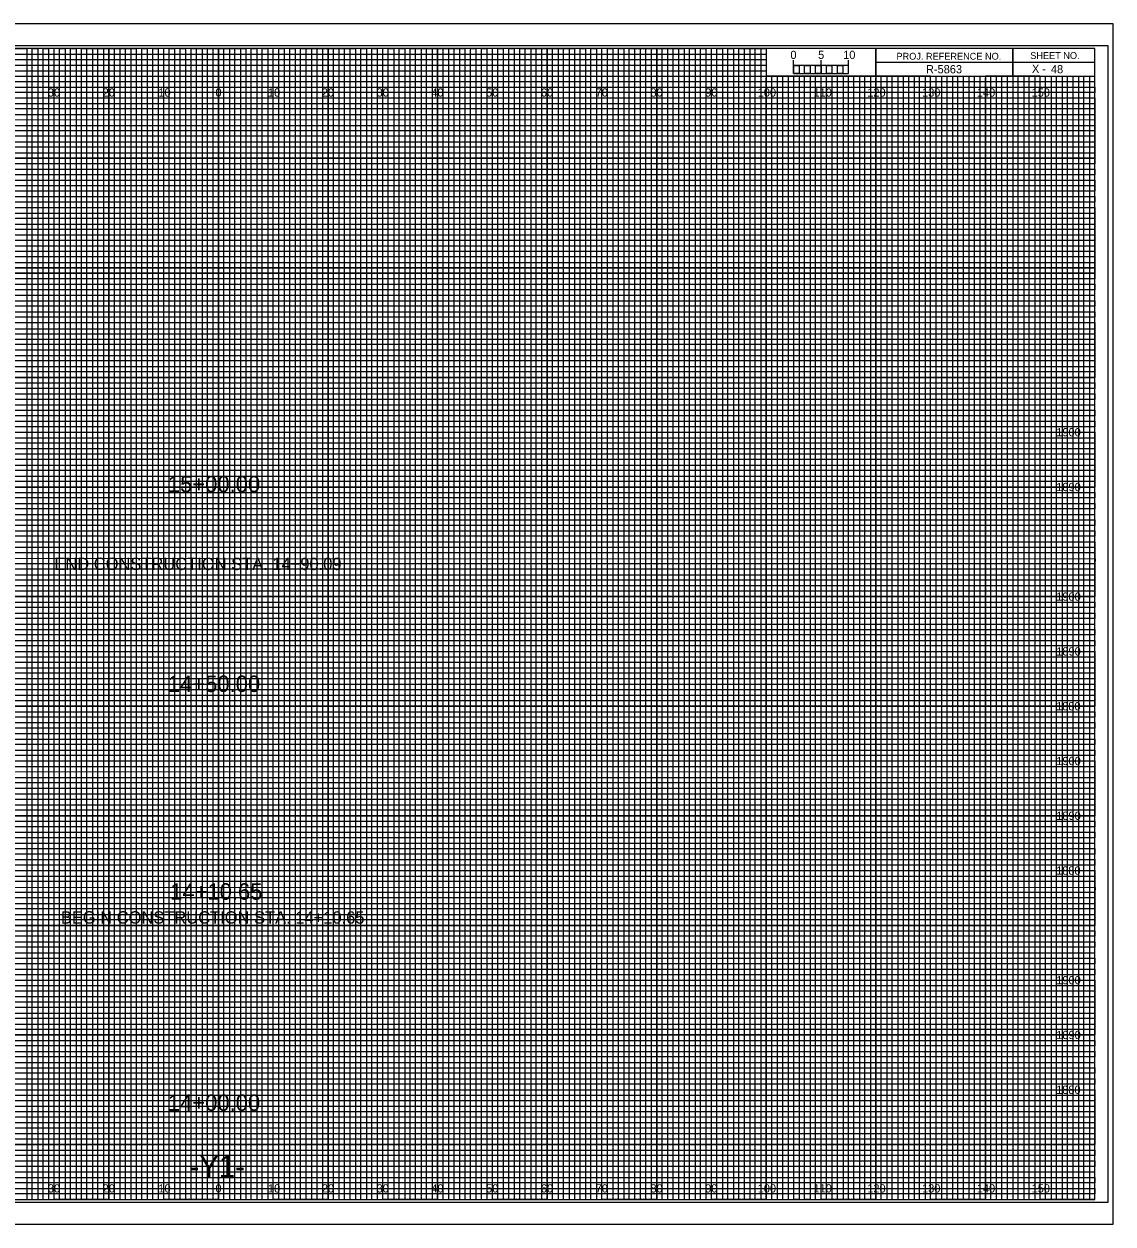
# Model space of a CAD drawing. Extents: x -13 to 323, y -4 to 214.
# Drawn here: x 124.5 to 323.3, y -4.5 to 214.5 of the extents above; entities that cross this region are included whole.
import ezdxf

# ---------------------------------------------------------------- set-up
doc = ezdxf.new("R2010")
doc.units = 0
for name, color, linetype in [('Prop XS Alignment Label', 7, 'Continuous'), ('Prop XS Bar Scale Labels', 7, 'Continuous'), ('Prop XS Elevation Labels', 7, 'Continuous'), ('Prop XS Offset Labels', 7, 'Continuous'), ('Prop XS Project Number', 7, 'Continuous'), ('Prop XS SE Text', 7, 'Continuous'), ('Prop XS Sheet Number', 7, 'Continuous'), ('Prop XS Station Labels', 7, 'Continuous'), ('Sheet Cross Section CELL', 7, 'Continuous'), ('Sheet Cross Section Grid Major CELL', 7, 'Continuous'), ('Sheet Cross Section Grid Middle CELL', 7, 'Continuous'), ('Sheet Cross Section Grid Minor 1 CELL', 7, 'Continuous'), ('Sheet Cross Section Grid Minor 2 CELL', 7, 'Continuous'), ('Sheet Cross Section Scale CELL', 7, 'Continuous'), ('Sheet Cutting Line CELL', 7, 'Continuous'), ('Sheet DOT Grid CELL', 7, 'Continuous'), ('Sheet Plot Border Inside CELL', 7, 'Continuous'), ('Sheet Plot Border Outside CELL', 7, 'Continuous')]:
    doc.layers.add(name, color=color, linetype=linetype)

msp = doc.modelspace()

# ---------------------------------------------------------------- linework, layer by layer
at = {"layer": 'Sheet Cross Section CELL'}
for p, q in [((305, 210), (305, 205)), ((305, 205), (305, 210)), ((280, 207.5), (280, 205)), ((320, 207.49), (280, 207.49)), ((280, 205), (320, 205))]:
    msp.add_line(p, q, dxfattribs=at)
for points in [[(320, 210), (0, 210), (0, 0), (320, 0)], [(280, 210), (260, 210), (260, 205.03), (280, 205.03)], [(320, 210), (280, 210), (280, 205), (320, 205)]]:
    msp.add_lwpolyline(points, close=True, dxfattribs=at)
at = {"layer": 'Sheet Cross Section Grid Major CELL'}
for p, q in [((130, 210), (120, 210)), ((130, 0), (130, 210)), ((150, 210), (140, 210)), ((140, 210), (140, 0)), ((150, 0), (150, 210)), ((170, 210), (160, 210)), ((160, 210), (160, 0)), ((170, 0), (170, 210)), ((190, 210), (180, 210)), ((180, 210), (180, 0)), ((190, 0), (190, 210)), ((210, 210), (200, 210)), ((200, 210), (200, 0)), ((210, 0), (210, 210)), ((230, 210), (220, 210)), ((220, 210), (220, 0)), ((230, 0), (230, 210)), ((250, 210), (240, 210)), ((240, 210), (240, 0)), ((250, 0), (250, 210)), ((260, 210), (260, 0)), ((270, 0), (270, 205)), ((290, 205), (280, 205)), ((280, 205), (280, 0)), ((290, 0), (290, 205)), ((310, 205), (300, 205)), ((300, 205), (300, 0)), ((310, 0), (310, 205)), ((140, 0), (130, 0)), ((160, 0), (150, 0)), ((180, 0), (170, 0)), ((200, 0), (190, 0)), ((220, 0), (210, 0)), ((240, 0), (230, 0)), ((260, 0), (250, 0)), ((280, 0), (270, 0)), ((300, 0), (290, 0)), ((320, 0), (310, 0)), ((320, 0), (320, 0))]:
    msp.add_line(p, q, dxfattribs=at)
for points in [[(0, 200), (320, 200), (320, 190), (0, 190)], [(0, 180), (320, 180), (320, 170), (0, 170)], [(0, 160), (320, 160), (320, 150), (0, 150)], [(0, 140), (320, 140), (320, 130), (0, 130)], [(0, 120), (320, 120), (320, 110), (0, 110)], [(0, 100), (320, 100), (320, 90), (0, 90)], [(0, 80), (320, 80), (320, 70), (0, 70)], [(0, 60), (320, 60), (320, 50), (0, 50)], [(0, 40), (320, 40), (320, 30), (0, 30)], [(0, 20), (320, 20), (320, 10), (0, 10)]]:
    msp.add_lwpolyline(points, dxfattribs=at)
at = {"layer": 'Sheet Cross Section Grid Middle CELL'}
for points in [[(115, 210), (125, 210), (125, 0), (135, 0), (135, 210), (145, 210), (145, 0), (155, 0), (155, 210), (165, 210), (165, 0), (175, 0), (175, 210), (185, 210), (185, 0), (195, 0), (195, 210), (205, 210), (205, 0), (215, 0), (215, 210), (225, 210), (225, 0), (235, 0), (235, 210), (245, 210), (245, 0), (255, 0), (255, 210), (259.93, 210), (260, 210), (260, 205), (264.99, 205), (264.99, 0), (275, 0), (275, 205), (285, 205), (285, 0), (295, 0), (295, 205), (305, 205), (305, 0), (315, 0), (315, 205)], [(0, 205), (275, 205)], [(0, 185), (320, 185), (320, 195), (0, 195)], [(0, 165), (320, 165), (320, 175), (0, 175)], [(0, 145), (320, 145), (320, 155), (0, 155)], [(0, 125), (320, 125), (320, 135), (0, 135)], [(0, 105), (320, 105), (320, 115), (0, 115)], [(0, 85), (320, 85), (320, 95), (0, 95)], [(0, 65), (320, 65), (320, 75), (0, 75)], [(0, 45), (320, 45), (320, 55), (0, 55)], [(0, 25), (320, 25), (320, 35), (0, 35)], [(0, 5), (320, 5), (320, 15), (0, 15)]]:
    msp.add_lwpolyline(points, dxfattribs=at)
at = {"layer": 'Sheet Cross Section Grid Minor 1 CELL'}
for p, q in [((0, 209), (260, 209)), ((260, 209), (260, 207.98)), ((260, 207.98), (0, 207.98)), ((0, 207), (260, 207)), ((260, 205.89), (0, 205.89)), ((260, 207), (260, 205.89)), ((0, 204), (320, 204))]:
    msp.add_line(p, q, dxfattribs=at)
for points in [[(0, 203), (270, 203), (320, 203), (320, 202), (0, 202)], [(0, 201), (320, 201), (320, 199), (0, 199)], [(0, 198), (320, 198), (320, 197), (0, 196.98)], [(0, 196), (320, 196), (320, 194), (0, 194)], [(0, 193), (320, 193), (320, 192), (0, 192)], [(0, 191), (320, 191), (320, 189), (0, 189)], [(0, 188), (320, 188), (320, 187), (0, 187)], [(0, 186), (320, 186), (320, 184), (0, 184)], [(0, 183), (320, 183), (320, 182), (0, 182)], [(0, 181), (320, 181), (320, 179), (0, 179)], [(0, 178), (320, 178), (320, 177), (0, 177)], [(0, 176), (320, 176), (320, 173.95), (320, 173), (320, 172), (0, 172)], [(0, 174), (320, 174), (320, 173), (0, 173)], [(0, 171), (320, 171), (320, 169), (0, 169.03)], [(0, 169.03), (320, 169), (320, 168), (0, 168)], [(0, 167), (320, 167), (320, 166), (0, 166)], [(0, 164), (320, 164), (320, 163), (0, 163)], [(0, 162), (320, 162), (320, 161), (0, 161)], [(-0.07, 158.89), (320, 158.89), (320, 157.88), (-0.07, 157.88)], [(0, 157), (320, 157), (320, 156), (0, 156)], [(0, 154), (320, 154), (320, 153), (0, 153)], [(0, 152), (320, 152), (320, 151), (0, 151)], [(0, 149), (320, 149), (320, 148), (0, 148)], [(0, 147), (320, 147), (320, 146), (0, 146)], [(0, 144), (320, 144), (320, 143), (0, 143)], [(0, 142), (320, 142), (320, 141), (0, 141)], [(0, 139), (320, 139), (319.99, 137.98), (0, 138)], [(0, 137), (320, 137), (320, 136), (0, 136)], [(0, 134), (320, 134), (320, 133), (0, 133)], [(0, 132), (320, 132), (320, 131), (0, 131)], [(0, 129), (320, 129), (320, 128), (0, 128)], [(0, 127), (320, 127), (320, 126), (0, 126)], [(0, 124), (320, 124), (320, 123), (0, 123)], [(0, 122), (320, 122), (320, 121), (0, 121)], [(0, 119), (320, 119), (320, 118), (0, 118)], [(0, 116.99), (320.07, 116.91), (320, 116), (0, 116)], [(0, 114), (320, 114), (320, 113), (0, 113)], [(0, 112), (320, 112), (320, 111), (0, 111)], [(0, 109), (320, 109), (320, 108), (0, 108)], [(0, 107), (320, 107), (320, 106), (0, 106)], [(0, 104), (320, 104), (320, 103), (0, 103)], [(0, 102), (320, 102), (320, 101), (0, 101)], [(0, 99), (320, 99), (320, 98), (0, 98)], [(0, 97), (320, 97), (320, 96), (0, 96)], [(0, 94), (320, 94), (320, 93), (0, 93)], [(0, 92), (320, 92), (320, 91), (0, 91)], [(0, 89), (320, 89), (320, 88), (0, 88)], [(0, 87), (320, 87), (320, 86), (0, 86)], [(0, 84), (320, 84), (320, 83), (0, 83)], [(0, 82), (320, 82), (320, 81), (0, 81)], [(0, 79), (320, 79), (319.99, 77.98), (0, 78)], [(0, 77), (320, 77), (320, 76), (0, 76)], [(0, 74), (320, 74), (320, 73), (0, 73)], [(0, 72), (320, 72), (320, 71), (0, 71)], [(0, 69), (320, 69), (320, 68), (0, 68)], [(0, 67), (320, 67), (320, 66), (0, 66)], [(0, 64), (320, 64), (320, 63), (0, 63)], [(0, 62), (320, 62), (320, 61), (0, 61)], [(0, 59), (320, 59), (320, 58), (0, 58)], [(0, 56.99), (320.07, 56.91), (320, 56), (0, 56)], [(0, 54), (320, 54), (320, 53), (0, 53)], [(0, 52), (320, 52), (320, 51), (0, 51)], [(0, 49), (320, 49), (320, 48), (0, 48)], [(0, 47), (320, 47), (320, 46), (0, 46)], [(0, 44), (320, 44), (320, 43), (0, 43)], [(0, 42), (320, 42), (320, 41), (0, 41)], [(0, 39), (320, 39), (320, 38), (0, 38)], [(0, 37), (320, 37), (320, 36), (0, 36)], [(0, 34), (320, 34), (320, 33), (0, 33)], [(0, 32), (320, 32), (320, 31), (0, 31)], [(0, 29), (320, 29), (320, 28), (0, 28)], [(0, 27), (320, 27), (320, 26), (0, 26)], [(0, 24), (320, 24), (320, 23), (0, 23)], [(0, 22), (320, 22), (320, 21), (0, 21)], [(0, 19), (320, 19), (320, 18), (0, 18)], [(0, 17), (320, 17), (320, 16), (0, 16)], [(0, 14), (320, 14), (320, 13), (0, 13)], [(0, 12), (320, 12), (320, 11), (0, 11)], [(0, 9), (320, 9), (320, 8), (0, 8)], [(0, 7), (320, 7), (320, 6), (0, 6)], [(0, 4), (320, 4), (320, 3), (0, 3)], [(0, 2), (320, 2), (320, 1), (0, 1)]]:
    msp.add_lwpolyline(points, dxfattribs=at)
at = {"layer": 'Sheet Cross Section Grid Minor 2 CELL'}
for p, q in [((267, 205), (266.01, 205)), ((266.01, 205), (266.01, 0)), ((267, 0), (267, 205)), ((269, 205), (268, 205)), ((268, 205), (268, 0)), ((269, 0), (269, 205)), ((266.01, 0), (265, 0)), ((268, 0), (267, 0))]:
    msp.add_line(p, q, dxfattribs=at)
for points in [[(125, 0), (126, 0), (126, 210), (127, 210), (127, 0)], [(127, 0), (128, 0), (128, 210), (129, 210), (129, 0)], [(130, 0), (131, 0), (131, 210), (132, 210), (132, 0)], [(132, 0), (133, 0), (133, 210), (134, 210), (134, 0)], [(135, 0), (136, 0), (136, 210), (137, 210), (137, 0)], [(137, 0), (138, 0), (138, 210), (139, 210), (139, 0)], [(140, 0), (141, 0), (141, 210), (142, 210), (142, 0)], [(142, 0), (143, 0), (143, 210), (144, 210), (144, 0)], [(145, 0), (146, 0), (146, 210), (147, 210), (147, 0)], [(147, 0), (148, 0), (148, 210), (149, 210), (149, 0)], [(150, 0), (151, 0), (151, 210), (152, 210), (152, 0)], [(152, 0), (153, 0), (153, 210), (154, 210), (154, 0)], [(155, 0), (156, 0), (156, 210), (157, 210), (157, 0)], [(157, 0), (158, 0), (158, 210), (159, 210), (159, 0)], [(160, 0), (161, 0), (161, 210), (162, 210), (162, 0)], [(162, 0), (163, 0), (163, 210), (164, 210), (164, 0)], [(165, 0), (166, 0), (166, 210), (167, 210), (167, 0)], [(167, 0), (168, 0), (168, 210), (169, 210), (169, 0)], [(170, 0), (171, 0), (171, 210), (172, 210), (172, 0)], [(172, 0), (173, 0), (173, 210), (174, 210), (174, 0)], [(175, 0), (176, 0), (176, 210), (177, 210), (177, 0)], [(177, 0), (178, 0), (178, 210), (179, 210), (179, 0)], [(180, 0), (181, 0), (181, 210), (182, 210), (182, 0)], [(182, 0), (183, 0), (183, 210), (184, 210), (184, 0)], [(185, 0), (186, 0), (186, 210), (187, 210), (187, 0)], [(187, 0), (188, 0), (188, 210), (189, 210), (189, 0)], [(190, 0), (191, 0), (191, 210), (192, 210), (192, 0)], [(192, 0), (193, 0), (193, 210), (194, 210), (194, 0)], [(195, 0), (196, 0), (196, 210), (197, 210), (197, 0)], [(197, 0), (198, 0), (198, 210), (199, 210), (199, 0)], [(200, 0), (201, 0), (201, 210), (202, 210), (202, 0)], [(202, 0), (203, 0), (203, 210), (204, 210), (204, 0)], [(205, 0), (206, 0), (206, 210), (207, 210), (207, 0)], [(207, 0), (208, 0), (208, 210), (209, 210), (209, 0)], [(210, 0), (211, 0), (211, 210), (212, 210), (212, 0)], [(212, 0), (213, 0), (213, 210), (214, 210), (214, 0)], [(215, 0), (216, 0), (216, 210), (217, 210), (217, 0)], [(217, 0), (218, 0), (218, 210), (219, 210), (219, 0)], [(220, 0), (221, 0), (221, 210), (222, 210), (222, 0)], [(222, 0), (223, 0), (223, 210), (224, 210), (224, 0)], [(225, 0), (226, 0), (226, 210), (227, 210), (227, 0)], [(227, 0), (228, 0), (228, 210), (229, 210), (229, 0)], [(230, 0), (231, 0), (231, 210), (232, 210), (232, 0)], [(232, 0), (233, 0), (233, 210), (234, 210), (234, 0)], [(235, 0), (236, 0), (236, 210), (237, 210), (237, 0)], [(237, 0), (238, 0), (238, 210), (239, 210), (239, 0)], [(240, 0), (241, 0), (241, 210), (242, 210), (242, 0)], [(242, 0), (243, 0), (243, 210), (244, 210), (244, 0)], [(245, 0), (246, 0), (246, 210), (247, 210), (247, 0)], [(247, 0), (248, 0), (248, 210), (249, 210), (249, 0)], [(250, 0), (251, 0), (251, 210), (252, 210), (252, 0)], [(252, 0), (253, 0), (253, 210), (254, 210), (254, 0)], [(255, 0), (256, 0), (256, 210), (257, 210), (257, 0)], [(257, 0), (258, 0), (258, 210), (259, 210), (259, 0)], [(260, 0), (261, 0), (261, 205), (262.02, 205), (262.02, 0)], [(262, 0), (263, 0), (263, 205), (263.99, 205), (263.99, 0)], [(270, 0), (270.98, 0), (270.98, 205), (272, 205), (272, 0)], [(272, 0), (273, 0), (273, 205), (274.05, 205), (274.05, 0)], [(275, 0), (276, 0), (276, 205), (277, 205), (277, 0)], [(277, 0), (278, 0), (278, 205), (279, 205), (279, 0)], [(280, 0), (281, 0), (281, 205), (282, 205), (282, 0)], [(282, 0), (283, 0), (283, 205), (284, 205), (284, 0)], [(285, 0), (286, 0), (286, 205), (287, 205), (287, 0)], [(287, 0), (288, 0), (288, 205), (289, 205), (289, 0)], [(290, 0), (291, 0), (291, 205), (292, 205), (292, 0)], [(292, 0), (293, 0), (293, 205), (294, 205), (294, 0)], [(295, 0), (296, 0), (296, 205), (297, 205), (297, 0)], [(297, 0), (298, 0), (298, 205), (299, 205), (299, 0)], [(300, 0), (301, 0), (301, 205), (302, 205), (302, 0)], [(302, 0), (303, 0), (303, 205), (304, 205), (304, 0)], [(305, 0), (306, 0), (306, 205), (307, 205), (307, 0)], [(307, 0), (308, 0), (308, 205), (309, 205), (309, 0)], [(310, 0), (311, 0), (311, 205), (312, 205), (312, 0)], [(312, 0), (313, 0), (313, 205), (314, 205), (314, 0)], [(315, 0), (316, 0), (316, 205), (317, 205), (317, 0)], [(317, 0), (318, 0), (318, 205), (319, 205), (319, 0)]]:
    msp.add_lwpolyline(points, dxfattribs=at)
at = {"layer": 'Sheet Cross Section Scale CELL'}
for p, q in [((265, 205.49), (265, 207.9)), ((265, 206.9), (265, 207.9)), ((270, 205.49), (270, 207.9)), ((275, 205.49), (275, 207.9)), ((275, 206.9), (275, 207.9))]:
    msp.add_line(p, q, dxfattribs=at)
for points in [[(275, 206.9), (265, 206.9), (265, 205.49), (275, 205.49)], [(265, 206.9), (266, 206.9), (266, 205.49), (265, 205.49)], [(267, 206.9), (268, 206.9), (268, 205.49), (267, 205.49)], [(269, 206.9), (270, 206.9), (270, 205.49), (269, 205.49)], [(271, 206.9), (272, 206.9), (272, 205.49), (271, 205.49)], [(273, 206.9), (274, 206.9), (274, 205.49), (273, 205.49)]]:
    msp.add_lwpolyline(points, close=True, dxfattribs=at)
at = {"layer": 'Sheet Cutting Line CELL'}
for p, q in [((323.3, 214.5), (-13.4, 214.5)), ((-13.4, -4.5), (323.3, -4.5))]:
    msp.add_line(p, q, dxfattribs=at)
at = {"layer": 'Sheet DOT Grid CELL'}
for p, q in [((130, 0), (130, 210)), ((140, 0), (140, 210)), ((150, 0), (150, 210)), ((160, 0), (160, 210)), ((170, 0), (170, 210)), ((180, 0), (180, 210)), ((190, 0), (190, 210)), ((200, 0), (200, 210)), ((210, 0), (210, 210)), ((220, 0), (220, 210)), ((230, 0), (230, 210)), ((240, 0), (240, 210)), ((250, 0), (250, 210)), ((260, 0), (260, 204.69)), ((270, 0), (270, 204.69)), ((280, 0), (280, 204.69)), ((290, 0), (290, 204.69)), ((300, 0), (300, 204.69)), ((310, 0), (310, 204.69)), ((0, 200), (320, 200)), ((0, 190), (320, 190)), ((0, 180), (320, 180)), ((0, 170), (320, 170)), ((0, 160), (320, 160)), ((0, 150), (320, 150)), ((0, 140), (320, 140)), ((0, 130), (320, 130)), ((0, 120), (320, 120)), ((0, 110), (320, 110)), ((0, 100), (320, 100)), ((0, 90), (320, 90)), ((0, 80), (320, 80)), ((0, 70), (320, 70)), ((0, 60), (320, 60)), ((0, 50), (320, 50)), ((0, 40), (320, 40)), ((0, 30), (320, 30)), ((0, 20), (320, 20)), ((0, 10), (320, 10))]:
    msp.add_line(p, q, dxfattribs=at)
at = {"layer": 'Sheet Plot Border Inside CELL'}
msp.add_lwpolyline([(-10.8, -0.5), (322.4, -0.5), (322.4, 210.5), (-10.8, 210.5)], close=True, dxfattribs=at)
at = {"layer": 'Sheet Plot Border Outside CELL'}
msp.add_lwpolyline([(-13.4, -4.5), (323.3, -4.5), (323.3, 214.5), (-13.4, 214.5)], close=True, dxfattribs=at)

# ---------------------------------------------------------------- texts
at = {"layer": 'Prop XS Alignment Label'}
msp.add_text('-Y1-', height=4, dxfattribs=at).set_placement((154.73, 4))
at = {"layer": 'Prop XS Bar Scale Labels'}
for s, p in [('5', (269.47, 208.12)), ('10', (274.04, 208.12))]:
    msp.add_text(s, height=1.5, dxfattribs=at).set_placement(p)
at = {"layer": 'Prop XS Elevation Labels'}
for s, p in [('1900', (312.95, 139.25)), ('1890', (312.95, 129.25)), ('1900', (312.95, 109.25)), ('1890', (312.95, 99.25)), ('1880', (312.92, 89.25)), ('1900', (312.95, 79.25)), ('1890', (312.95, 69.25)), ('1880', (312.92, 59.25)), ('1900', (312.95, 39.25)), ('1890', (312.95, 29.25)), ('1880', (312.92, 19.25))]:
    msp.add_text(s, height=1.5, dxfattribs=at).set_placement(p)
at = {"layer": 'Prop XS Offset Labels'}
for s, p in [('30', (128.86, 201.25)), ('20', (138.86, 201.25)), ('10', (149.04, 201.25)), ('0', (159.45, 201.25)), ('0', (159.45, 201.25)), ('10', (169.04, 201.25)), ('20', (178.86, 201.25)), ('30', (188.86, 201.25)), ('40', (198.86, 201.25)), ('50', (208.86, 201.25)), ('60', (218.86, 201.25)), ('70', (228.86, 201.25)), ('80', (238.86, 201.25)), ('90', (248.86, 201.25)), ('100', (258.44, 201.25)), ('110', (268.62, 201.25)), ('120', (278.44, 201.25)), ('130', (288.44, 201.25)), ('140', (298.44, 201.25)), ('150', (308.44, 201.25)), ('30', (128.86, 1.25)), ('20', (138.86, 1.25)), ('10', (149.04, 1.25)), ('0', (159.45, 1.25)), ('0', (159.45, 1.25)), ('10', (169.04, 1.25)), ('20', (178.86, 1.25)), ('30', (188.86, 1.25)), ('40', (198.86, 1.25)), ('50', (208.86, 1.25)), ('60', (218.86, 1.25)), ('70', (228.86, 1.25)), ('80', (238.86, 1.25)), ('90', (248.86, 1.25)), ('100', (258.44, 1.25)), ('110', (268.62, 1.25)), ('120', (278.44, 1.25)), ('130', (288.44, 1.25)), ('140', (298.44, 1.25)), ('150', (308.44, 1.25))]:
    msp.add_text(s, height=1.5, dxfattribs=at).set_placement(p)
at = {"layer": 'Prop XS Project Number'}
msp.add_text('R-5863', height=1.5, dxfattribs=at).set_placement((289.16, 205.5))
at = {"layer": 'Prop XS SE Text'}
for s, p in [('END CONSTRUCTION STA. 14+90.09', (130.05, 114.86)), ('BEGIN CONSTRUCTION STA. 14+10.65', (131.23, 50.33))]:
    msp.add_text(s, height=2.25, rotation=359.9789, dxfattribs=at).set_placement(p)
at = {"layer": 'Prop XS Sheet Number'}
msp.add_text('48', height=1.5, dxfattribs=at).set_placement((311.97, 205.5))
at = {"layer": 'Prop XS Station Labels'}
for s, p in [('15+00.00', (150.77, 129.04)), ('14+50.00', (150.77, 92.59)), ('14+10.65', (151.18, 54.68)), ('14+00.00', (150.77, 16.14))]:
    msp.add_text(s, height=3, dxfattribs=at).set_placement(p)
at = {"layer": 'Sheet Cross Section CELL'}
for s, height, p in [('PROJ. REFERENCE NO.', 1.25, (283.77, 207.99)), ('SHEET NO.', 1.25, (308.19, 208.12)), ('X -    ', 1.5, (308.5, 205.58))]:
    msp.add_text(s, height=height, dxfattribs=at).set_placement(p)
at = {"layer": 'Sheet Cross Section Scale CELL'}
msp.add_text('0', height=1.5, dxfattribs=at).set_placement((264.41, 208.12))

doc.saveas('drawing.dxf')
